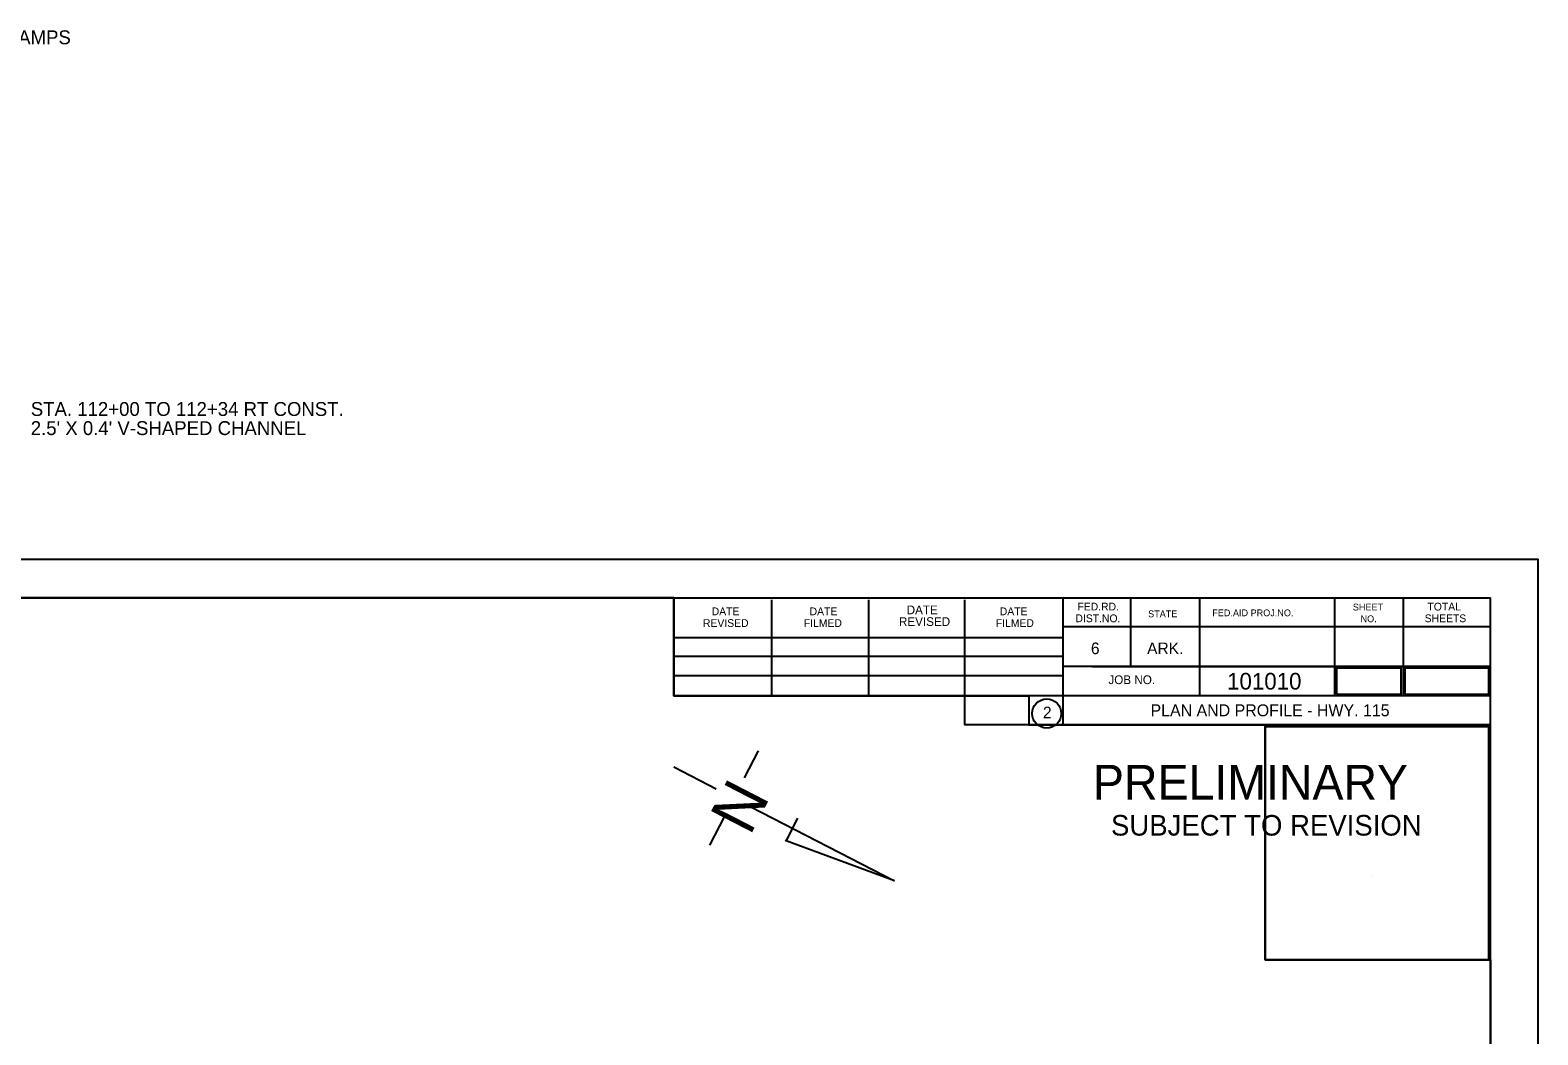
# Model space of a CAD drawing. Extents: x 9709 to 12772, y 9986 to 11806.
# Drawn here: x 10855 to 11615, y 10813 to 11320 of the extents above; entities that cross this region are included whole.
import ezdxf

# ---------------------------------------------------------------- set-up
doc = ezdxf.new("R2010")
doc.units = 0
for name, color, linetype in [('GREEN_TXT', 7, 'Continuous'), ('NOTES', 7, 'Continuous'), ('Page Number', 7, 'Continuous'), ('R_Border Notes', 7, 'Continuous'), ('R_Border PE', 7, 'Continuous'), ('R_No Plot', 7, 'Continuous'), ('SEAL-INFO', 7, 'Continuous'), ('SIGNATURE', 7, 'Continuous'), ('TEXT', 7, 'Continuous'), ('Total_Pages', 7, 'Continuous')]:
    doc.layers.add(name, color=color, linetype=linetype)

msp = doc.modelspace()

# ---------------------------------------------------------------- linework, layer by layer
for p, q in [((11222.21, 10956.52), (11215.13, 10942.81)), ((11179.68, 10948.35), (11200.94, 10937.39)), ((11218.46, 10928.34), (11290.76, 10891.04)), ((11205.23, 10923.61), (11197.68, 10908.97)), ((11242.02, 10922.54), (11236.09, 10911.05)), ((11290.76, 10891.04), (11235.71, 10911.25))]:
    msp.add_line(p, q)
at = {"layer": 'GREEN_TXT'}
for p, q in [((10010.16, 11033.62), (11591.06, 11033.62)), ((11179.76, 10984.22), (11179.76, 11033.62)), ((11229.06, 10984.22), (11229.06, 11032.62)), ((11277.86, 10984.22), (11277.86, 11032.62)), ((11326.26, 10984.22), (11326.26, 11032.62)), ((11375.56, 11033.62), (11375.56, 10969.62)), ((11409.76, 11033.62), (11409.76, 10998.92)), ((11444.46, 11033.62), (11444.46, 10984.22)), ((11512.36, 11033.62), (11512.36, 10984.22)), ((11547.06, 11033.62), (11547.06, 10984.22)), ((11591.06, 10006.32), (11591.06, 11033.62)), ((11591.06, 11018.92), (11375.56, 11018.92)), ((11591.06, 11019.02), (11591.06, 11019.02)), ((11179.76, 11013.52), (11375.56, 11013.52)), ((11179.76, 11004.22), (11375.56, 11004.22)), ((11591.06, 10998.92), (11375.56, 10998.92)), ((11390.36, 10998.92), (11591.06, 10998.92)), ((11179.76, 10984.22), (11179.76, 10994.52)), ((11179.76, 10994.52), (11375.56, 10994.52)), ((11591.06, 10984.22), (11179.76, 10984.22)), ((11375.56, 10969.62), (11591.06, 10969.62))]:
    msp.add_line(p, q, dxfattribs=at)
msp.add_circle((11367.49, 10975.3), 7.33, dxfattribs=at)
at = {"layer": 'Page Number'}
msp.add_lwpolyline([(11513.38, 10984.97), (11546.03, 10984.97), (11546.03, 10998.17), (11513.38, 10998.17)], close=True, dxfattribs=at)
at = {"layer": 'R_No Plot'}
msp.add_line((9948.15, 11053.09), (11614.82, 11053.09), dxfattribs=at)
for points in [[(9948.15, 11053.12), (11614.85, 11053.12), (11614.85, 9986.43), (9948.15, 9986.43)], [(11179.76, 11033.62), (11179.76, 10984.22), (11358.42, 10984.22), (11358.42, 10969.62), (11477.57, 10969.62), (11477.57, 10851.23), (11591.06, 10851.23), (11591.06, 10521.02), (10010.16, 10521.02), (10010.16, 11033.62)], [(11477.57, 10968.72), (11589.93, 10968.72), (11589.93, 10851.23), (11477.57, 10851.23)]]:
    msp.add_lwpolyline(points, close=True, dxfattribs=at)
at = {"layer": 'SEAL-INFO'}
msp.add_lwpolyline([(11326.26, 10984.22), (11179.76, 10984.22), (11179.76, 11033.62), (10010.16, 11033.62), (10010.16, 10521.02), (11297.46, 10521.02), (11591.06, 10521.02), (11591.06, 10556.02), (11591.06, 10556.02), (11591.06, 10969.62), (11326.26, 10969.62)], close=True, dxfattribs=at)
at = {"layer": 'Total_Pages'}
msp.add_lwpolyline([(11547.88, 10984.97), (11590.24, 10984.97), (11590.24, 10998.17), (11547.88, 10998.17)], close=True, dxfattribs=at)

# ---------------------------------------------------------------- texts
msp.add_text('N', height=23.27, rotation=242.71029).set_placement((11207.62, 10943.87))
at = {"layer": 'GREEN_TXT'}
for s, height, p in [('DATE', 3.91, (11198.76, 11024.82)), ('DATE', 3.91, (11248.06, 11024.82)), ('DATE', 4.396, (11296.96, 11025.32)), ('DATE', 3.91, (11343.86, 11024.82)), ('FED.RD.', 3.91, (11382.96, 11027.22)), ('STATE', 3.42, (11418.56, 11023.82)), ('FED.AID PROJ.NO.', 3.42, (11450.86, 11024.32)), ('SHEET', 3.42, (11521.66, 11027.22)), ('TOTAL', 3.91, (11559.26, 11027.22)), ('REVISED', 3.91, (11194.36, 11018.92)), ('FILMED', 3.91, (11245.16, 11018.92)), ('REVISED', 4.396, (11293.06, 11019.42)), ('FILMED', 3.91, (11341.86, 11018.92)), ('DIST.NO.', 3.91, (11381.96, 11021.32)), ('NO.', 3.42, (11525.56, 11021.32)), ('SHEETS', 3.91, (11557.86, 11021.32)), ('6', 5.86, (11389.76, 11005.22)), ('ARK.', 5.861, (11418.06, 11005.22)), ('JOB NO.', 4.396, (11398.56, 10990.12)), ('2', 5.86, (11365.58, 10972.87))]:
    msp.add_text(s, height=height, rotation=360, dxfattribs=at).set_placement(p)
at = {"layer": 'NOTES'}
for s, p in [('STA. 112+00 TO 112+34 RT CONST.', (10855.79, 11125.24)), ("2.5' X 0.4' V-SHAPED CHANNEL ", (10855.79, 11115.61))]:
    msp.add_text(s, height=7, dxfattribs=at).set_placement(p)
at = {"layer": 'R_Border Notes'}
msp.add_text('101010', height=8.4, dxfattribs=at).set_placement((11458.33, 10987.37))
msp.add_text('PLAN AND PROFILE - HWY. 115', height=6, rotation=360, dxfattribs=at).set_placement((11419.78, 10973.92))
at = {"layer": 'R_Border PE'}
for p in [(11522.62, 10930.77), (11530.97, 10930.78), (11539.79, 10930.71), (11522.6, 10892.9), (11530.94, 10892.92), (11539.78, 10892.85)]:
    msp.add_text('DWB', height=0.1, rotation=360, dxfattribs=at).set_placement(p)
at = {"layer": 'SIGNATURE'}
for s, height, p in [('PRELIMINARY', 17.5, (11390.81, 10931.94)), ('DWB', 0.1, (11394.55, 10941.18)), ('SUBJECT TO REVISION', 10.3756, (11399.86, 10913.79))]:
    msp.add_text(s, height=height, rotation=360, dxfattribs=at).set_placement(p)
at = {"layer": 'TEXT'}
msp.add_text('FOR THE CONSTRUCTION OF TEMPORARY RAMPS', height=7, dxfattribs=at).set_placement((10643.51, 11312.54))

doc.saveas('drawing.dxf')
